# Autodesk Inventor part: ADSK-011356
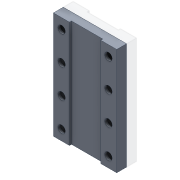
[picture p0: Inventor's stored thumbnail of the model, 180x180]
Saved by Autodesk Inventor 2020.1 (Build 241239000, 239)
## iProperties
Created: 1999-12
Part Number: ADSK-011356
Material: Pearson Aluminium
Description: PLT-08,FA,AX,05,051,030,CLAMP,BELT
Document SubType Name: Modeling
Designer: sspink
Density: 2.71 g/cm^3
Appearance: Pearson-Aluminum
Mass: 253.438 g
Surface Area: 285.016 cm^2
Volume: 93.5197 cm^3
Control State: 0
Checked Out: False
Master: False
Shininess: 35.0
Length Units: 11269
Angle Units: 11279
Time Units: 11290
Mass Units: 11283
Length Display Precision: 3
Angle Display Precision: 2
Compacted: True
Dimensions: 77x130x12 mm
Mass: 0,253 kg
DocNumber: ADSK-011356.ipt
Folder: 01 - Themengebiete\Simplification\01 - Packaging machine\
VDS_Category: 3D Komponenten
Density: 2.71
Volumn: 117.4790993251019
Area: 270.36169177141903
PropertySet Name: Model Information
Author: sspink
Revision Number: -
Title: PLT-08,FA,AX,05,051,030,CLAMP,BELT
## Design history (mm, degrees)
node "Solide1"
  node "Extrusion1" dims "d2" = 12, "d3" = 0
  node "Hole1" dims "d16" = 9, "d17" = 15, "d18" = 9, "d19" = 60 deg, "d20" = 19.05, "d21" = 118 deg, "d28" = 6
sketch "Sketch1"
  geometry: L1 (38.5, -65)-(-38.5, -65); L2 (-38.5, -65)-(-38.5, 65); L3 (-38.5, 65)-(38.5, 65); L4 (38.5, 65)-(38.5, -65); 3 further points
  constraints: 8 end point, 2 midpoint, 2 parallel, 1 horizontal, 1 horizontal alignment, 1 perpendicular, 1 vertical alignment
  dimensions: "d0" = 77 distance between parallel lines of L4 L2; "d1" = 130 distance of L1.end L2.end
sketch "Sketch3"
  geometry: L1 (-28.5, 52.5)-(28.5, 52.5); L2 (28.5, 52.5)-(28.5, -52.5); L3 (28.5, -52.5)-(-28.5, -52.5); L4 (-28.5, -52.5)-(-28.5, 52.5); L5 (-38.5, -65)-(-38.5, 65) reference; L6 (-38.5, 65)-(38.5, 65) reference; 10 further points
  constraints: 8 end point, 6 vertical alignment, 4 horizontal alignment, 4 midpoint, 2 parallel, 1 coincident, 1 horizontal, 1 perpendicular
  dimensions: "d24" = 57 distance of L1.start L1.end; "d25" = 105 distance of L3.end L1.start; "d26" = 35 distance from line of L1 point (-28.5, 17.5) (= 0.333333 x d25); "d27" = 35 distance of point (-28.5, 17.5) point (-28.5, -17.5) (= 0.333333 x d25)
sketch "Skizze4"
  geometry: L1 (38.5, -65)-(-38.5, -65) reference; L2 (38.5, 65)-(38.5, -65) reference; L3 (-38.5, 65)-(38.5, 65) reference; L4 (-38.5, -65)-(-38.5, 65) reference; L5 (19, -65)-(-19, -65); L6 (-19, -65)-(-19, 65); L7 (-19, 65)-(19, 65); L8 (19, 65)-(19, -65); L9 (38.5, -65)-(-38.5, -65) reference; 3 further points
  constraints: 8 end point, 2 midpoint, 2 parallel, 2 point on line, 1 coincident, 1 horizontal, 1 perpendicular
  dimensions: "d29" = 38 distance between parallel lines of L6 L8
extrude "Extrusion3" cut sketch "Skizze4" distance "d30" = 2.5; taper "d31" = 0 deg
workplane "Work Plane1"
workplane "Work Plane2"
node "Projizierte Kontur1"
node "Corps solides"
node "Corps surfaciques"
other parameters: "d22" = -19.05, "d23" = -19.05
